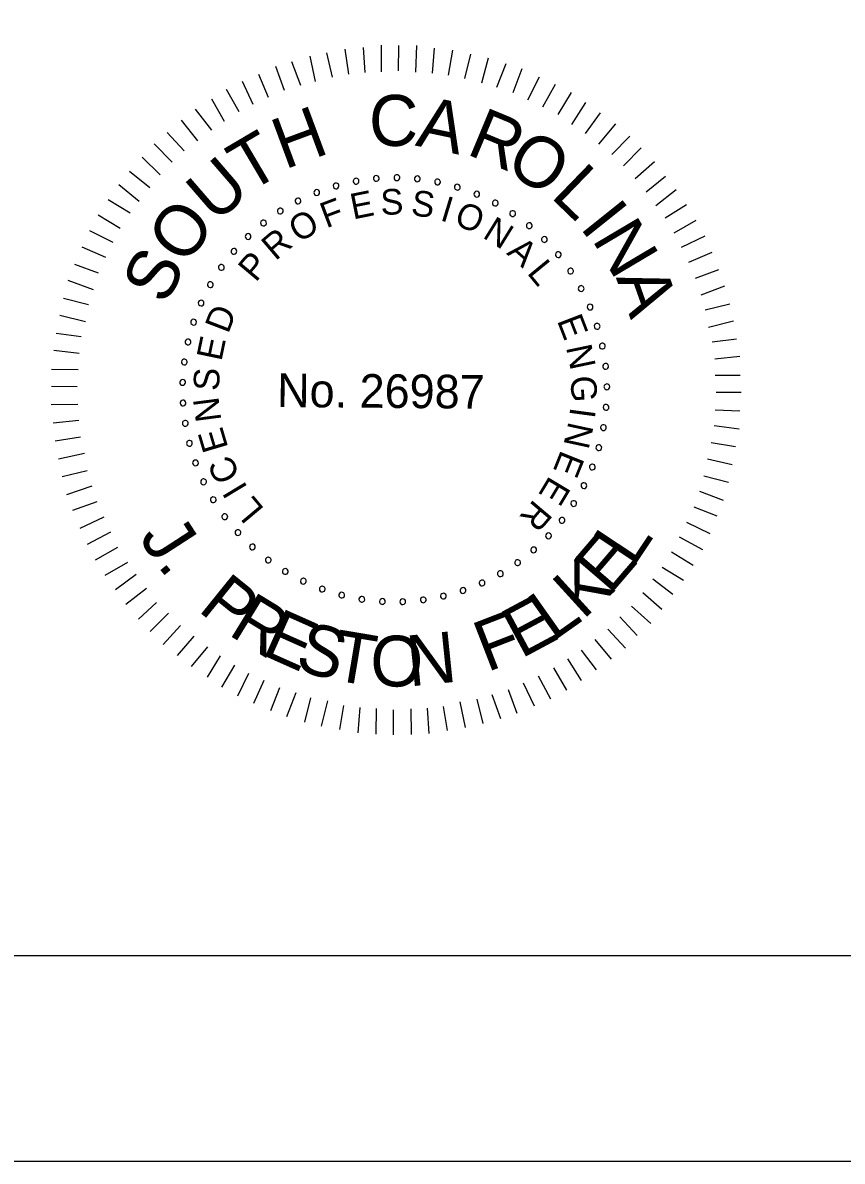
# Model space of a CAD drawing. Extents: x -305 to -161, y -187 to -99.
# Drawn here: x -211.56 to -203.6, y -187.49 to -176.42 of the extents above; entities that cross this region are included whole.
import ezdxf

# ---------------------------------------------------------------- set-up
doc = ezdxf.new("R2010")
doc.units = 0
for name, color, linetype in [('BR_BORDER LINES', 7, 'Continuous'), ('BR_TEXT', 7, 'Continuous'), ('Level 31', 7, 'Continuous')]:
    doc.layers.add(name, color=color, linetype=linetype)

msp = doc.modelspace()

# ---------------------------------------------------------------- linework, layer by layer
at = {"layer": 'BR_BORDER LINES'}
msp.add_line((-297.843, -185.489), (-163.178, -185.489), dxfattribs=at)
at = {"layer": 'BR_TEXT'}
for p, q in [((-208.552, -176.946), (-208.608, -176.709)), ((-208.394, -176.917), (-208.429, -176.673)), ((-208.236, -176.901), (-208.251, -176.657)), ((-208.077, -176.892), (-208.075, -176.634)), ((-207.909, -176.883), (-207.907, -176.636)), ((-207.741, -176.895), (-207.732, -176.637)), ((-207.58, -176.906), (-207.561, -176.663)), ((-207.426, -176.925), (-207.382, -176.681)), ((-207.265, -176.957), (-207.208, -176.721)), ((-208.861, -177.026), (-208.949, -176.795)), ((-208.717, -176.986), (-208.77, -176.742)), ((-207.1, -176.999), (-207.036, -176.756)), ((-206.953, -177.042), (-206.865, -176.813)), ((-209.175, -177.144), (-209.269, -176.92)), ((-209.02, -177.076), (-209.103, -176.842)), ((-206.795, -177.095), (-206.708, -176.862)), ((-206.652, -177.165), (-206.54, -176.942)), ((-209.323, -177.211), (-209.427, -176.987)), ((-206.508, -177.234), (-206.383, -177.012)), ((-209.602, -177.377), (-209.724, -177.16)), ((-209.461, -177.282), (-209.582, -177.065)), ((-206.358, -177.308), (-206.229, -177.093)), ((-209.726, -177.462), (-209.883, -177.258)), ((-206.225, -177.405), (-206.089, -177.19)), ((-209.861, -177.564), (-210.021, -177.363)), ((-206.091, -177.492), (-205.946, -177.291)), ((-209.993, -177.662), (-210.159, -177.482)), ((-205.962, -177.596), (-205.799, -177.398)), ((-210.11, -177.771), (-210.287, -177.594)), ((-205.836, -177.696), (-205.663, -177.519)), ((-205.723, -177.807), (-205.55, -177.634)), ((-210.228, -177.894), (-210.402, -177.724)), ((-205.611, -177.932), (-205.421, -177.765)), ((-210.328, -178.02), (-210.526, -177.864)), ((-205.502, -178.06), (-205.316, -177.907)), ((-210.432, -178.153), (-210.63, -177.993)), ((-205.407, -178.194), (-205.21, -178.038)), ((-210.519, -178.269), (-210.735, -178.137)), ((-205.319, -178.312), (-205.109, -178.183)), ((-210.617, -178.416), (-210.832, -178.287)), ((-205.231, -178.46), (-205.017, -178.335)), ((-210.686, -178.552), (-210.912, -178.441)), ((-205.16, -178.598), (-204.929, -178.49)), ((-210.756, -178.699), (-210.985, -178.598)), ((-205.089, -178.746), (-204.862, -178.648)), ((-210.826, -178.853), (-211.059, -178.766)), ((-205.022, -178.901), (-204.795, -178.817)), ((-210.876, -179.014), (-211.122, -178.923)), ((-204.968, -179.063), (-204.738, -178.976)), ((-210.925, -179.158), (-211.168, -179.098)), ((-204.928, -179.207), (-204.688, -179.151)), ((-210.954, -179.326), (-211.204, -179.262)), ((-204.895, -179.376), (-204.654, -179.316)), ((-210.996, -179.47), (-211.24, -179.437)), ((-204.862, -179.52), (-204.625, -179.491)), ((-211.015, -179.634), (-211.261, -179.605)), ((-204.836, -179.685), (-204.592, -179.66)), ((-211.026, -179.792), (-211.284, -179.79)), ((-204.831, -179.843), (-204.59, -179.845)), ((-211.034, -179.957), (-211.285, -179.955)), ((-204.822, -180.008), (-204.578, -180.01)), ((-211.029, -180.129), (-211.286, -180.133)), ((-204.833, -180.18), (-204.593, -180.189)), ((-211.02, -180.283), (-211.267, -180.312)), ((-204.841, -180.334), (-204.598, -180.367)), ((-211.004, -180.448), (-211.248, -180.484)), ((-204.87, -180.499), (-204.634, -180.538)), ((-210.964, -180.606), (-211.215, -180.659)), ((-204.906, -180.656), (-204.666, -180.713)), ((-210.938, -180.775), (-211.182, -180.831)), ((-210.891, -180.923), (-211.139, -181.006)), ((-204.942, -180.824), (-204.702, -180.885)), ((-204.984, -180.971), (-204.755, -181.059)), ((-210.845, -181.077), (-211.079, -181.161)), ((-205.04, -181.125), (-204.814, -181.213)), ((-210.777, -181.226), (-211.008, -181.334)), ((-210.71, -181.37), (-210.937, -181.489)), ((-205.11, -181.272), (-204.884, -181.384)), ((-205.183, -181.416), (-204.954, -181.538)), ((-210.642, -181.519), (-210.859, -181.644)), ((-205.257, -181.563), (-205.045, -181.692)), ((-210.547, -181.667), (-210.765, -181.792)), ((-210.462, -181.784), (-210.663, -181.93)), ((-205.347, -181.71), (-205.139, -181.839)), ((-210.361, -181.919), (-210.561, -182.075)), ((-205.437, -181.826), (-205.243, -181.975)), ((-205.535, -181.959), (-205.351, -182.118)), ((-210.262, -182.054), (-210.439, -182.217)), ((-205.645, -182.092), (-205.458, -182.258)), ((-210.146, -182.158), (-210.326, -182.338)), ((-205.76, -182.194), (-205.589, -182.377)), ((-210.031, -182.279), (-210.2, -182.463)), ((-205.874, -182.313), (-205.704, -182.5)), ((-209.901, -182.383), (-210.064, -182.57)), ((-206.002, -182.415), (-205.842, -182.605)), ((-209.768, -182.487), (-209.928, -182.678)), ((-209.645, -182.574), (-209.77, -182.782)), ((-206.133, -182.517), (-205.99, -182.71)), ((-209.505, -182.664), (-209.63, -182.879)), ((-206.402, -182.69), (-206.277, -182.907)), ((-206.268, -182.602), (-206.135, -182.812)), ((-209.368, -182.744), (-209.477, -182.967)), ((-209.221, -182.814), (-209.319, -183.037)), ((-206.554, -182.768), (-206.432, -182.992)), ((-209.068, -182.884), (-209.155, -183.11)), ((-206.843, -182.902), (-206.759, -183.13)), ((-206.699, -182.835), (-206.591, -183.059)), ((-208.91, -182.933), (-209.001, -183.166)), ((-208.766, -182.983), (-208.823, -183.219)), ((-208.602, -183.011), (-208.662, -183.258)), ((-207.315, -183.022), (-207.262, -183.27)), ((-207.15, -182.996), (-207.09, -183.233)), ((-207.002, -182.949), (-206.918, -183.183)), ((-208.444, -183.057), (-208.484, -183.29)), ((-208.287, -183.076), (-208.306, -183.323)), ((-208.129, -183.087), (-208.131, -183.335)), ((-207.961, -183.099), (-207.963, -183.343)), ((-207.792, -183.09), (-207.787, -183.338)), ((-207.631, -183.081), (-207.616, -183.329)), ((-207.476, -183.065), (-207.437, -183.299))]:
    msp.add_line(p, q, dxfattribs=at)
for centre, start, end in [((-208.323, -177.957), 10.6038, 190.6038), ((-208.126, -177.93), 5.0653, 185.0653), ((-208.126, -177.93), 185.0653, 5.0653), ((-207.926, -177.923), 359.5268, 179.5268), ((-207.926, -177.923), 179.5268, 359.5268), ((-207.727, -177.934), 173.9884, 353.9884), ((-207.727, -177.934), 353.9884, 173.9884), ((-207.531, -177.965), 348.4499, 168.4499), ((-208.706, -178.067), 21.6807, 201.6807), ((-208.517, -178.003), 16.1422, 196.1422), ((-208.517, -178.003), 196.1422, 16.1422), ((-208.323, -177.957), 190.6038, 10.6038), ((-207.531, -177.965), 168.4499, 348.4499), ((-207.338, -178.015), 162.9114, 342.9114), ((-207.338, -178.015), 342.9114, 162.9114), ((-208.887, -178.149), 27.2191, 207.2191), ((-208.887, -178.149), 207.2191, 27.2191), ((-208.706, -178.067), 201.6807, 21.6807), ((-207.15, -178.083), 157.373, 337.373), ((-207.15, -178.083), 337.373, 157.373), ((-206.97, -178.169), 151.8345, 331.8345), ((-206.97, -178.169), 331.8345, 151.8345), ((-209.06, -178.248), 32.7576, 212.7576), ((-209.06, -178.248), 212.7576, 32.7576), ((-206.8, -178.272), 146.2961, 326.2961), ((-206.8, -178.272), 326.2961, 146.2961), ((-209.223, -178.364), 38.2961, 218.2961), ((-209.223, -178.364), 218.2961, 38.2961), ((-206.639, -178.39), 140.7576, 320.7576), ((-206.639, -178.39), 320.7576, 140.7576), ((-209.373, -178.495), 43.8345, 223.8345), ((-209.373, -178.495), 223.8345, 43.8345), ((-206.492, -178.524), 315.2191, 135.2191), ((-206.492, -178.524), 135.2191, 315.2191), ((-209.511, -178.639), 49.373, 229.373), ((-209.511, -178.639), 229.373, 49.373), ((-206.357, -178.671), 129.6807, 309.6807), ((-206.357, -178.671), 309.6807, 129.6807), ((-209.633, -178.796), 54.9114, 234.9114), ((-209.633, -178.796), 234.9114, 54.9114), ((-206.238, -178.831), 124.1422, 304.1422), ((-206.238, -178.831), 304.1422, 124.1422), ((-209.74, -178.964), 60.4499, 240.4499), ((-209.74, -178.964), 240.4499, 60.4499), ((-206.135, -179.001), 118.6038, 298.6038), ((-206.135, -179.001), 298.6038, 118.6038), ((-209.83, -179.142), 65.9884, 245.9884), ((-209.83, -179.142), 245.9884, 65.9884), ((-206.048, -179.181), 113.0653, 293.0653), ((-206.048, -179.181), 293.0653, 113.0653), ((-209.903, -179.328), 71.5268, 251.5268), ((-209.903, -179.328), 251.5268, 71.5268), ((-205.979, -179.368), 107.5268, 287.5268), ((-205.979, -179.368), 287.5268, 107.5268), ((-209.957, -179.52), 77.0653, 257.0653), ((-209.957, -179.52), 257.0653, 77.0653), ((-205.929, -179.561), 101.9884, 281.9884), ((-205.929, -179.561), 281.9884, 101.9884), ((-209.993, -179.716), 82.6038, 262.6038), ((-209.993, -179.716), 262.6038, 82.6038), ((-205.897, -179.758), 96.4499, 276.4499), ((-205.897, -179.758), 276.4499, 96.4499), ((-210.009, -179.914), 88.1422, 268.1422), ((-210.009, -179.914), 268.1422, 88.1422), ((-205.885, -179.957), 90.9114, 270.9114), ((-205.885, -179.957), 270.9114, 90.9114), ((-210.006, -180.114), 93.6807, 273.6807), ((-210.006, -180.114), 273.6807, 93.6807), ((-205.892, -180.156), 85.373, 265.373), ((-205.892, -180.156), 265.373, 85.373), ((-209.984, -180.312), 99.2191, 279.2191), ((-209.984, -180.312), 279.2191, 99.2191), ((-205.918, -180.353), 79.8345, 259.8345), ((-205.918, -180.353), 259.8345, 79.8345), ((-209.943, -180.507), 104.7576, 284.7576), ((-209.943, -180.507), 284.7576, 104.7576), ((-205.963, -180.548), 74.2961, 254.2961), ((-205.963, -180.548), 254.2961, 74.2961), ((-209.884, -180.697), 110.2961, 290.2961), ((-209.884, -180.697), 290.2961, 110.2961), ((-206.026, -180.737), 68.7576, 248.7576), ((-206.026, -180.737), 248.7576, 68.7576), ((-209.806, -180.881), 115.8345, 295.8345), ((-209.806, -180.881), 295.8345, 115.8345), ((-206.108, -180.918), 63.2191, 243.2191), ((-206.108, -180.918), 243.2191, 63.2191), ((-209.711, -181.056), 121.373, 301.373), ((-209.711, -181.056), 301.373, 121.373), ((-206.207, -181.092), 57.6807, 237.6807), ((-206.207, -181.092), 237.6807, 57.6807), ((-209.599, -181.221), 126.9114, 306.9114), ((-209.599, -181.221), 306.9114, 126.9114), ((-206.321, -181.255), 52.1422, 232.1422), ((-206.321, -181.255), 232.1422, 52.1422), ((-209.472, -181.375), 132.4499, 312.4499), ((-209.472, -181.375), 312.4499, 132.4499), ((-206.452, -181.406), 46.6038, 226.6038), ((-206.452, -181.406), 226.6038, 46.6038), ((-209.331, -181.515), 137.9884, 317.9884), ((-209.331, -181.515), 317.9884, 137.9884), ((-206.596, -181.543), 41.0653, 221.0653), ((-206.596, -181.543), 221.0653, 41.0653), ((-209.177, -181.642), 143.5268, 323.5268), ((-209.177, -181.642), 323.5268, 143.5268), ((-206.752, -181.667), 35.5268, 215.5268), ((-206.752, -181.667), 215.5268, 35.5268), ((-209.011, -181.753), 149.0653, 329.0653), ((-209.011, -181.753), 329.0653, 149.0653), ((-206.92, -181.774), 29.9884, 209.9884), ((-206.92, -181.774), 209.9884, 29.9884), ((-208.836, -181.847), 154.6038, 334.6038), ((-208.836, -181.847), 334.6038, 154.6038), ((-208.652, -181.924), 160.1422, 340.1422), ((-208.652, -181.924), 340.1422, 160.1422), ((-207.283, -181.938), 18.9114, 198.9114), ((-207.098, -181.865), 24.4499, 204.4499), ((-207.098, -181.865), 204.4499, 24.4499), ((-208.462, -181.983), 165.6807, 345.6807), ((-208.462, -181.983), 345.6807, 165.6807), ((-208.267, -182.023), 171.2191, 351.2191), ((-208.267, -182.023), 351.2191, 171.2191), ((-208.068, -182.045), 356.7576, 176.7576), ((-207.869, -182.047), 2.2961, 182.2961), ((-207.67, -182.029), 7.8345, 187.8345), ((-207.67, -182.029), 187.8345, 7.8345), ((-207.474, -181.993), 13.373, 193.373), ((-207.474, -181.993), 193.373, 13.373), ((-207.283, -181.938), 198.9114, 18.9114), ((-208.068, -182.045), 176.7576, 356.7576), ((-207.869, -182.047), 182.2961, 2.2961)]:
    msp.add_arc(centre, 0.028, start, end, dxfattribs=at)
at = {"layer": 'Level 31'}
msp.add_lwpolyline([(-305.176, -187.489), (-161.176, -187.489), (-161.176, -99.489), (-305.176, -99.489)], close=True, dxfattribs=at)

# ---------------------------------------------------------------- texts
at = {"layer": 'BR_TEXT'}
for s, height, rotation, p in [('C', 0.496, 359.5482, (-208.2, -177.612)), ('A', 0.496, 348.1981, (-207.755, -177.609)), ('H', 0.496, 20.3637, (-209.018, -177.846)), ('R', 0.496, 337.4344, (-207.262, -177.689)), ('T', 0.496, 30.4992, (-209.37, -178.076)), ('O', 0.496, 326.5869, (-206.893, -177.836)), ('U', 0.496, 40.8022, (-209.694, -178.375)), ('L', 0.496, 315.9488, (-206.442, -178.107)), ('E', 0.249, 11.4103, (-208.352, -178.33)), ('S', 0.249, 2.208, (-208.081, -178.286)), ('S', 0.249, 352.6608, (-207.796, -178.287)), ('F', 0.249, 20.6127, (-208.613, -178.417)), ('I', 0.249, 343.1136, (-207.515, -178.335)), ('I', 0.496, 308.6613, (-206.157, -178.404)), ('O', 0.496, 52.0267, (-209.993, -178.79)), ('O', 0.249, 30.8477, (-208.882, -178.561)), ('O', 0.249, 338.4392, (-207.381, -178.376)), ('N', 0.249, 328.2042, (-207.103, -178.501)), ('N', 0.496, 300.7037, (-206.035, -178.521)), ('R', 0.249, 40.3949, (-209.107, -178.737)), ('A', 0.249, 318.657, (-206.867, -178.662)), ('S', 0.496, 63.2511, (-210.174, -179.173)), ('P', 0.249, 49.9421, (-209.299, -178.947)), ('L', 0.249, 309.4546, (-206.668, -178.851)), ('A', 0.496, 289.4792, (-205.798, -178.894)), ('D', 0.249, 69.0364, (-209.567, -179.448)), ('E', 0.249, 291.049, (-206.372, -179.312)), ('E', 0.249, 78.2388, (-209.633, -179.715)), ('N', 0.249, 281.8466, (-206.283, -179.572)), ('S', 0.249, 87.786, (-209.656, -179.999)), ('No. 26987', 0.327, 359.5268, (-209.092, -180.153)), ('G', 0.249, 272.2995, (-206.237, -179.853)), ('N', 0.249, 97.3332, (-209.632, -180.283)), ('I', 0.249, 262.4084, (-206.238, -180.149)), ('E', 0.249, 106.5355, (-209.564, -180.549)), ('N', 0.249, 257.7339, (-206.256, -180.287)), ('E', 0.249, 248.1867, (-206.328, -180.563)), ('C', 0.249, 116.4266, (-209.444, -180.819)), ('I', 0.249, 121.1011, (-209.372, -180.939)), ('E', 0.249, 238.9844, (-206.44, -180.814)), ('L', 0.249, 129.9595, (-209.209, -181.147)), ('R', 0.249, 229.782, (-206.591, -181.044)), ('J', 0.494, 302.9559, (-210.441, -181.421)), ('E', 0.494, 49.3639, (-205.857, -181.989)), ('L', 0.494, 56.4247, (-205.627, -181.718)), ('K', 0.494, 42.3031, (-206.118, -182.229)), ('.', 0.494, 309.3974, (-210.264, -181.693)), ('P', 0.494, 321.1035, (-209.871, -182.13)), ('R', 0.494, 328.5359, (-209.578, -182.362)), ('E', 0.494, 28.1814, (-206.719, -182.605)), ('L', 0.494, 35.2422, (-206.407, -182.436)), ('E', 0.494, 335.9684, (-209.257, -182.555)), ('F', 0.494, 21.1206, (-207.05, -182.735)), ('S', 0.494, 343.0292, (-208.932, -182.698)), ('T', 0.494, 350.4617, (-208.573, -182.804)), ('O', 0.494, 358.1419, (-208.192, -182.863)), ('N', 0.494, 5.8221, (-207.805, -182.872))]:
    msp.add_text(s, height=height, rotation=rotation, dxfattribs=at).set_placement(p)

doc.saveas('drawing.dxf')
